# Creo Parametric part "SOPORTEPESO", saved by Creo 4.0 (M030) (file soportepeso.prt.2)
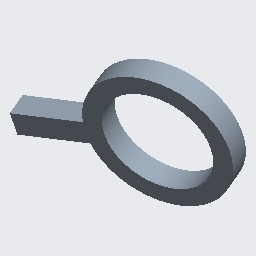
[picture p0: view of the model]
Units: millimeter Newton Second (mmNs); MM, TONNE, SECS

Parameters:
  MODELED_BY = "AJ"

Created from: MMNS_PART_SOLID.PRT

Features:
  1. datum plane "RIGHT"
  2. datum plane "TOP"
  3. datum plane "FRONT"
  4. coordinate system
  5. extrusion "Extrude 1"
  6. extrusion "Extrude 2"
  7. extrusion "Extrude 3"
  8. extrusion "Extrude 4"

Surfaces: 5 plane, 1 cylinder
